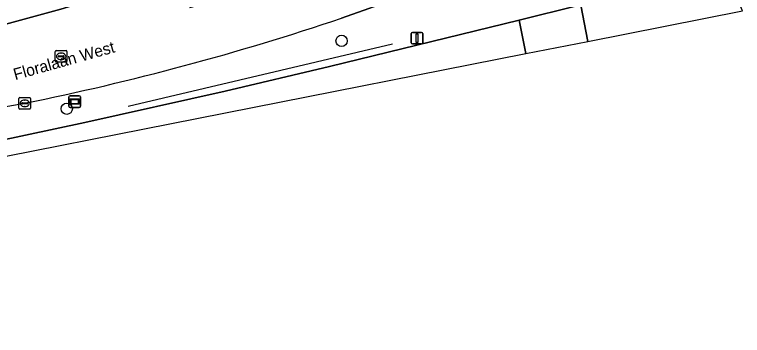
# Model space of a CAD drawing. Extents: x 162250 to 162661, y 380743 to 381606.
# Drawn here: x 162559.7 to 162622.4, y 380743.5 to 380771.1 of the extents above; entities that cross this region are included whole.
import ezdxf

# ---------------------------------------------------------------- set-up
doc = ezdxf.new("R2010")
doc.units = 0
for name, color, linetype in [('IMGEO_Berm_groen', 7, 'Continuous'), ('IMGEO_Boom', 7, 'Continuous'), ('IMGEO_Fietspad_gesloten', 7, 'Continuous'), ('IMGEO_Hek', 7, 'Continuous'), ('IMGEO_Kolk', 7, 'Continuous'), ('IMGEO_Openbare_ruimte_label', 7, 'Continuous'), ('IMGEO_Rijbaan_lokaal_gesloten', 7, 'Continuous'), ('IMGEO_Rioolput', 7, 'Continuous'), ('IMGEO_Straatnaambord', 7, 'Continuous'), ('IMGEO_Verkeersbordpaal', 7, 'Continuous')]:
    doc.layers.add(name, color=color, linetype=linetype)

msp = doc.modelspace()

# ---------------------------------------------------------------- linework, layer by layer
at = {"layer": 'IMGEO_Berm_groen'}
for points in [[(162612.263, 380779.501), (162587.836, 380770.829)], [(162545.049, 380757.511), (162555.492, 380759.638), (162565.725, 380761.839), (162577.823, 380764.52), (162586.784, 380766.654), (162603.142, 380770.658), (162608.222, 380771.902), (162608.434, 380771.951), (162614.363, 380773.32)]]:
    msp.add_lwpolyline(points, dxfattribs=at)
for centre, radius, start, end in [((162515.448, 380985.413), 226.465, 281.48792, 288.64137), ((162518.165, 381009.725), 249.861, 276.15299, 279.76679)]:
    msp.add_arc(centre, radius, start, end, dxfattribs=at)
at = {"layer": 'IMGEO_Boom'}
for centre in [(162587.834, 380768.865), (162564.169, 380763.013)]:
    msp.add_circle(centre, 0.489, dxfattribs=at)
at = {"layer": 'IMGEO_Fietspad_gesloten'}
msp.add_lwpolyline([(162577.139, 380778.323), (162568.051, 380775.78), (162558.545, 380772.543), (162557.877, 380772.36), (162555.57, 380772.19), (162555.673, 380769.819), (162555.675, 380769.767), (162556.593, 380769.86), (162558.605, 380770.207), (162563.646, 380771.598), (162566.197, 380772.406), (162569.236, 380773.491), (162570.219, 380773.77), (162579.513, 380776.404)], dxfattribs=at)
at = {"layer": 'IMGEO_Hek'}
msp.add_lwpolyline([(162592.229, 380768.585), (162569.458, 380763.214)], dxfattribs=at)
at = {"layer": 'IMGEO_Kolk'}
for p, q in [((162560.05, 380763.059), (162560.05, 380763.911)), ((162560.125, 380763.985), (162560.977, 380763.985)), ((162560.538, 380763.765), (162560.563, 380763.765)), ((162561.051, 380763.911), (162561.051, 380763.059)), ((162560.977, 380762.985), (162560.125, 380762.985)), ((162560.309, 380763.479), (162560.309, 380763.491)), ((162560.747, 380763.442), (162560.349, 380763.442)), ((162560.352, 380763.528), (162560.75, 380763.528)), ((162560.561, 380763.205), (162560.536, 380763.205)), ((162560.793, 380763.491), (162560.793, 380763.479))]:
    msp.add_line(p, q, dxfattribs=at)
for points in [[(162560.05, 380763.059), (162560.05, 380763.911)], [(162560.125, 380763.985), (162560.977, 380763.985)], [(162561.051, 380763.911), (162561.051, 380763.059)], [(162560.977, 380762.985), (162560.125, 380762.985)]]:
    msp.add_lwpolyline(points, dxfattribs=at)
for centre, radius, start, end in [((162560.127, 380763.909), 0.0765, 91.55205, 178.44795), ((162560.127, 380763.909), 0.0765, 91.55205, 178.44795), ((162560.975, 380763.909), 0.0765, 1.55205, 88.44795), ((162560.975, 380763.909), 0.0765, 1.55205, 88.44795), ((162560.127, 380763.061), 0.0765, 181.55205, 268.44795), ((162560.127, 380763.061), 0.0765, 181.55205, 268.44795), ((162560.349, 380763.488), 0.0403, 85.87752, 175.75265), ((162560.346, 380763.478), 0.0366, 178.93798, 274.71019), ((162560.75, 380763.485), 0.043, 264.86636, 352.45326), ((162560.754, 380763.49), 0.0386, 1.73085, 96.63898), ((162560.975, 380763.061), 0.0765, 271.55205, 358.44795), ((162560.975, 380763.061), 0.0765, 271.55205, 358.44795)]:
    msp.add_arc(centre, radius, start, end, dxfattribs=at)
for centre, major_axis, ratio, start_param, end_param in [((162560.537, 380763.485), (-0.387, 0.002), 0.722429, 4.712389, 7.853982), ((162560.562, 380763.485), (-0.39, 0.002), 0.717154, 1.570796, 4.712389)]:
    msp.add_ellipse(centre, major_axis=major_axis, ratio=ratio, start_param=start_param, end_param=end_param, dxfattribs=at)
at = {"layer": 'IMGEO_Rijbaan_lokaal_gesloten'}
for points in [[(162587.836, 380770.829), (162612.263, 380779.501), (162615.33, 380780.589), (162615.431, 380780.626), (162618.556, 380781.738), (162617.87, 380786.235), (162617.369, 380786.001), (162614.519, 380785.002), (162611.509, 380783.932), (162610.603, 380783.611), (162591.689, 380776.935), (162588.644, 380775.876), (162586.064, 380775.028), (162582.557, 380773.958), (162578.092, 380772.645), (162575.942, 380772.035), (162574.748, 380771.72)], [(162609.055, 380768.819), (162622.355, 380771.442), (162620.912, 380774.806), (162617.55, 380774.048), (162614.363, 380773.32), (162608.434, 380771.951), (162609.055, 380768.819)], [(162569.236, 380773.491), (162566.197, 380772.406), (162563.646, 380771.598), (162558.605, 380770.207), (162556.593, 380769.86)], [(162450.181, 380743.589), (162467.626, 380743.47), (162503.413, 380748.389), (162530.539, 380753.513), (162551.953, 380757.558), (162603.709, 380767.765), (162603.142, 380770.658), (162586.784, 380766.654), (162577.823, 380764.52), (162565.725, 380761.839), (162555.492, 380759.638), (162545.049, 380757.511), (162526.321, 380753.781)]]:
    msp.add_lwpolyline(points, dxfattribs=at)
msp.add_lwpolyline([(162609.055, 380768.819), (162608.434, 380771.951), (162608.222, 380771.902), (162603.142, 380770.658), (162603.709, 380767.765)], close=True, dxfattribs=at)
for centre, radius, start, end in [((162515.448, 380985.413), 226.465, 281.48792, 288.64137), ((162518.165, 381009.725), 249.861, 276.15299, 279.76679)]:
    msp.add_arc(centre, radius, start, end, dxfattribs=at)
at = {"layer": 'IMGEO_Rioolput'}
for p, q in [((162563.185, 380767.108), (162563.185, 380767.96)), ((162563.26, 380768.034), (162564.112, 380768.034)), ((162564.186, 380767.96), (162564.186, 380767.108)), ((162563.444, 380767.528), (162563.444, 380767.54)), ((162563.882, 380767.491), (162563.484, 380767.491)), ((162563.487, 380767.577), (162563.885, 380767.577)), ((162563.673, 380767.814), (162563.698, 380767.814)), ((162563.928, 380767.54), (162563.928, 380767.528)), ((162564.112, 380767.034), (162563.26, 380767.034)), ((162563.696, 380767.254), (162563.671, 380767.254))]:
    msp.add_line(p, q, dxfattribs=at)
for points in [[(162563.185, 380767.108), (162563.185, 380767.96)], [(162563.26, 380768.034), (162564.112, 380768.034)], [(162564.186, 380767.96), (162564.186, 380767.108)], [(162564.112, 380767.034), (162563.26, 380767.034)]]:
    msp.add_lwpolyline(points, dxfattribs=at)
for centre, radius, start, end in [((162563.262, 380767.958), 0.0765, 91.55205, 178.44795), ((162563.262, 380767.958), 0.0765, 91.55205, 178.44795), ((162564.11, 380767.958), 0.0765, 1.55205, 88.44795), ((162564.11, 380767.958), 0.0765, 1.55205, 88.44795), ((162563.484, 380767.537), 0.0403, 85.87752, 175.75265), ((162563.481, 380767.527), 0.0366, 178.93798, 274.71019), ((162563.885, 380767.534), 0.043, 264.86636, 352.45326), ((162563.889, 380767.539), 0.0386, 1.73085, 96.63898), ((162563.262, 380767.11), 0.0765, 181.55205, 268.44795), ((162563.262, 380767.11), 0.0765, 181.55205, 268.44795), ((162564.11, 380767.11), 0.0765, 271.55205, 358.44795), ((162564.11, 380767.11), 0.0765, 271.55205, 358.44795)]:
    msp.add_arc(centre, radius, start, end, dxfattribs=at)
for centre, major_axis, ratio, start_param, end_param in [((162563.672, 380767.534), (-0.387, 0.002), 0.722429, 4.712389, 7.853982), ((162563.697, 380767.534), (-0.39, 0.002), 0.717154, 1.570796, 4.712389)]:
    msp.add_ellipse(centre, major_axis=major_axis, ratio=ratio, start_param=start_param, end_param=end_param, dxfattribs=at)
at = {"layer": 'IMGEO_Straatnaambord'}
for p, q in [((162564.349, 380763.228), (162564.349, 380764.028)), ((162564.349, 380764.028), (162564.349, 380763.228)), ((162564.449, 380764.128), (162565.239, 380764.128)), ((162565.239, 380764.128), (162564.449, 380764.128)), ((162565.339, 380764.028), (162565.339, 380763.228)), ((162565.339, 380763.228), (162565.339, 380764.028)), ((162565.239, 380763.128), (162564.449, 380763.128)), ((162564.449, 380763.128), (162565.239, 380763.128))]:
    msp.add_line(p, q, dxfattribs=at)
for points in [[(162564.45, 380763.86), (162565.238, 380763.86), (162565.238, 380763.396), (162564.45, 380763.396), (162564.45, 380763.86)], [(162564.515, 380763.795), (162564.515, 380763.461), (162565.173, 380763.461), (162565.173, 380763.795), (162564.515, 380763.795)]]:
    msp.add_lwpolyline(points, dxfattribs=at)
for centre, start, end in [((162564.449, 380764.028), 90, 180), ((162564.449, 380764.028), 90, 180), ((162565.239, 380764.028), 0, 90), ((162565.239, 380764.028), 360, 90), ((162564.449, 380763.228), 180, 270), ((162564.449, 380763.228), 180, 270), ((162565.239, 380763.228), 270, 0), ((162565.239, 380763.228), 270, 0)]:
    msp.add_arc(centre, 0.1, start, end, dxfattribs=at)
at = {"layer": 'IMGEO_Verkeersbordpaal'}
for p, q in [((162593.839, 380768.7), (162593.839, 380769.5)), ((162593.839, 380769.5), (162593.839, 380768.7)), ((162593.939, 380769.6), (162594.729, 380769.6)), ((162594.729, 380769.6), (162593.939, 380769.6)), ((162594.829, 380769.5), (162594.829, 380768.7)), ((162594.829, 380768.7), (162594.829, 380769.5)), ((162594.729, 380768.6), (162593.939, 380768.6)), ((162593.939, 380768.6), (162594.729, 380768.6))]:
    msp.add_line(p, q, dxfattribs=at)
msp.add_lwpolyline([(162594.259, 380769.475), (162594.409, 380769.475), (162594.409, 380768.725), (162594.259, 380768.725), (162594.259, 380769.475)], dxfattribs=at)
for centre, start, end in [((162593.939, 380769.5), 90, 180), ((162593.939, 380769.5), 90, 180), ((162594.729, 380769.5), 0, 90), ((162594.729, 380769.5), 360, 90), ((162593.939, 380768.7), 180, 270), ((162593.939, 380768.7), 180, 270), ((162594.729, 380768.7), 270, 0), ((162594.729, 380768.7), 270, 0)]:
    msp.add_arc(centre, 0.1, start, end, dxfattribs=at)

# ---------------------------------------------------------------- texts
at = {"layer": 'IMGEO_Openbare_ruimte_label'}
msp.add_text('Floralaan West', height=1, rotation=15.66211, dxfattribs=at).set_placement((162559.73, 380765.471))

doc.saveas('drawing.dxf')
